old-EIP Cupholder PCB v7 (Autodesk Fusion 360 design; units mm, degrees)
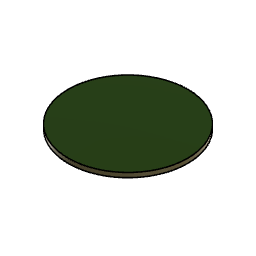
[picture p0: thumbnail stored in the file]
derived_context "DerivedContext1"
sketch "Outline" plane through (0, 0, 0) normal (0, 0, 1) x axis (1, 0, 0)
step sketch "pcb-sketch"
canvas "Canvas1" bodies "Board"
canvas "Canvas2" bodies "Board"
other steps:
pcbextrude "PCBExtrude"
pcbextrude "PCBExtrude1"
derived_base_feature "pcb-sketch"
box_primitive "BoxPrimitive1" DistanceX 8 DistanceY 3.81 DistanceZ 0.1 OffsetDistanceX 0 OffsetDistanceY 0
base_feature "Base Feature"
box_primitive "BoxPrimitive1" DistanceX 20 DistanceY 17.95 DistanceZ 1 OffsetDistanceX 0 OffsetDistanceY 0
pcbextrude "PCBExtrude1"
pcbextrude "PCBExtrude1"
extrude "Extrude1" sketch "pcb-sketch" blind 1.5 bodies "Board"
pcbextrude "PCBExtrude1"
pcbextrude "PCBExtrude"
create_component "CreateComponent1"
create_component "CreateComponent2"
create_component "CreateComponent3"
create_component "CreateComponent4"
create_component "CreateComponent5"
create_component "CreateComponent6"
create_component "CreateComponent3"
as_built_joint "As-built1"
create_component "CreateComponent5"
create_component "CreateComponent6"
named bodies: "Board"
